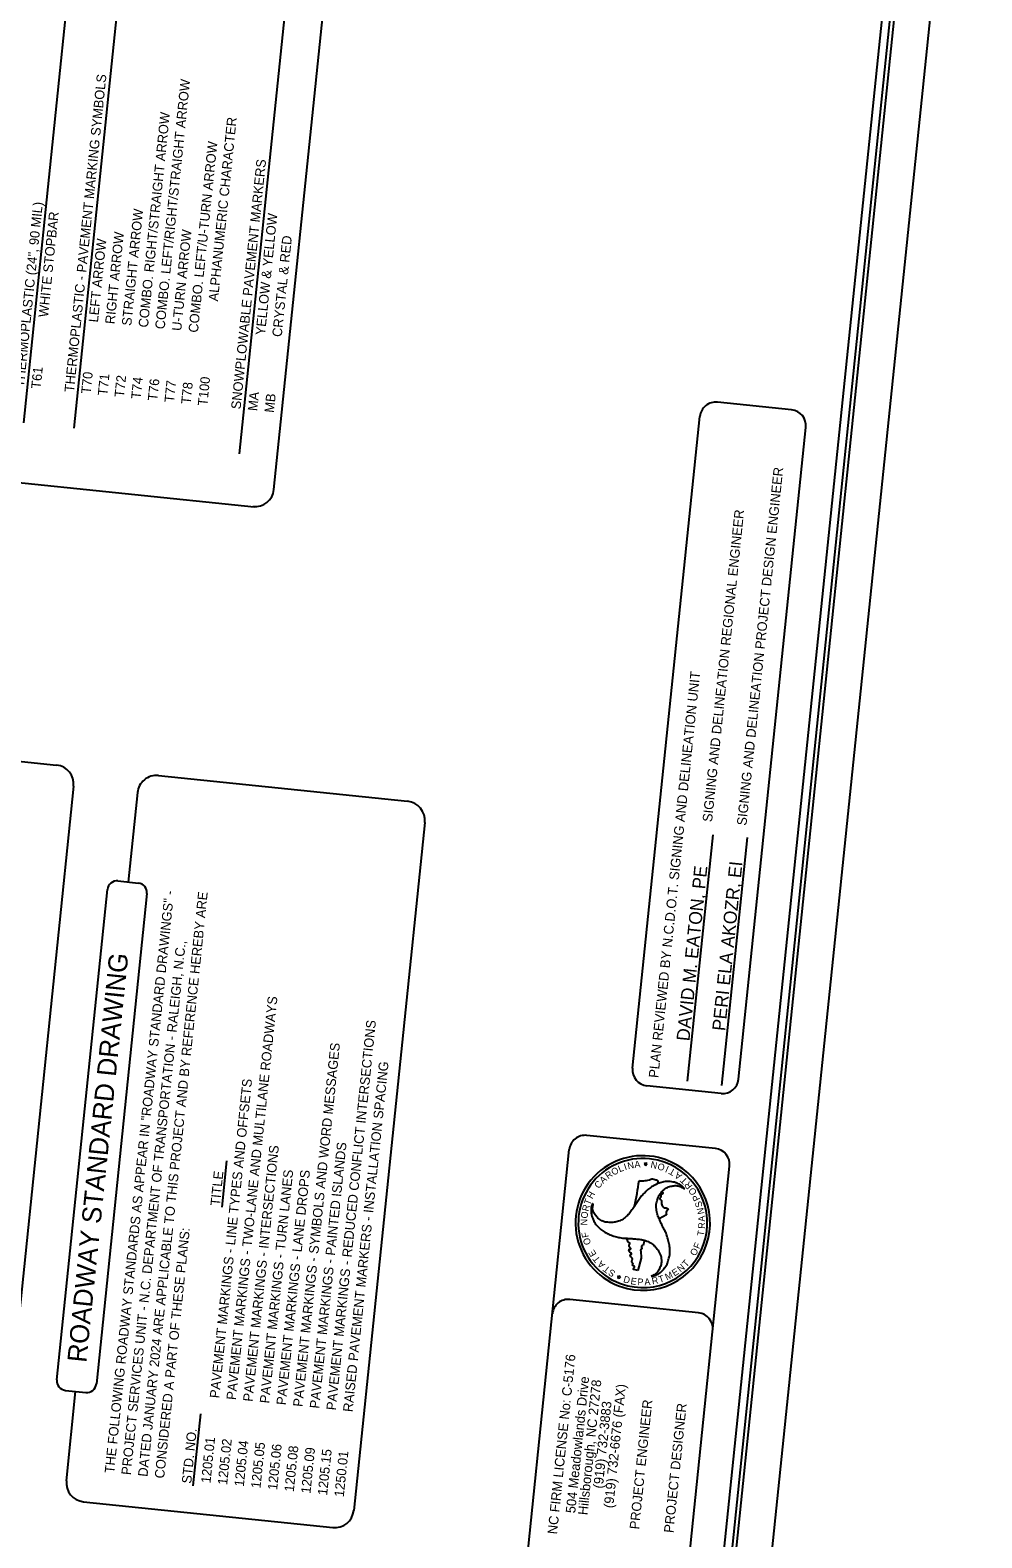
# Model space of a CAD drawing. Extents: x 2077770 to 2079037, y 247476 to 249877.
# Drawn here: x 2078441 to 2079037, y 248438 to 249383 of the extents above; entities that cross this region are included whole.
import ezdxf

# ---------------------------------------------------------------- set-up
doc = ezdxf.new("R2010")
doc.units = 0
for name, color, linetype in [('Default', 7, 'Continuous'), ('Prop DSN Text', 7, 'Continuous'), ('Sheet Data Field CELL', 7, 'Continuous'), ('Sheet Plot Border Inside CELL', 7, 'Continuous'), ('Sheet Plot Border Outside CELL', 7, 'Continuous'), ('Sheet Title CELL', 7, 'Continuous')]:
    doc.layers.add(name, color=color, linetype=linetype)

msp = doc.modelspace()

# ---------------------------------------------------------------- linework, layer by layer
at = {"layer": 'Default'}
for p, q in [((2078437.01, 249136.79), (2078468.87, 249445.46)), ((2078468.6, 249133.53), (2078500.46, 249442.19)), ((2078572.22, 249117.41), (2078604.08, 249426.08))]:
    msp.add_line(p, q, dxfattribs=at)
at = {"layer": 'Prop DSN Text'}
for p, q in [((2078561.18, 248645.5), (2078564.18, 248674.51)), ((2078543.17, 248470.98), (2078547.83, 248516.12))]:
    msp.add_line(p, q, dxfattribs=at)
at = {"layer": 'Sheet Plot Border Inside CELL'}
msp.add_lwpolyline([(2078843.53, 248043.45), (2079014.62, 249701.14), (2077965.1, 249809.47), (2077794, 248151.77)], close=True, dxfattribs=at)
at = {"layer": 'Sheet Plot Border Outside CELL'}
msp.add_lwpolyline([(2077943.23, 249816.25), (2077770.34, 248141.15), (2078864.51, 248028.21), (2079037.4, 249703.31)], close=True, dxfattribs=at)
at = {"layer": 'Sheet Title CELL'}
for p, q in [((2078858.5, 248262.08), (2079004.29, 249674.56)), ((2078593.75, 249095.03), (2078631.89, 249464.62)), ((2078918.18, 249144.97), (2078871.67, 249149.77)), ((2078818.55, 248732.54), (2078860.7, 249140.85)), ((2078884.96, 248725.69), (2078927.1, 249133.99)), ((2078214.68, 249121.93), (2078581.25, 249084.28)), ((2078190.95, 248949.99), (2078457.5, 248922.48)), ((2078468.2, 248909.31), (2078423.72, 248478.31)), ((2078521.32, 248915.9), (2078677.53, 248899.76)), ((2078508.16, 248905.2), (2078502.38, 248849.22)), ((2078688.23, 248886.59), (2078643.75, 248455.6)), ((2078852.97, 248724.49), (2078868.92, 248878.82)), ((2078874.45, 248721.72), (2078890.49, 248877.14)), ((2078457.7, 248537.42), (2078489.4, 248844.53)), ((2078514.12, 248841.98), (2078482.43, 248534.86)), ((2078495.98, 248849.88), (2078508.77, 248848.56)), ((2078873.99, 248716.77), (2078827.47, 248721.57)), ((2078870.42, 248682.21), (2078789.83, 248690.53)), ((2078738.74, 248293), (2078778.85, 248681.61)), ((2078826.46, 248672.82), (2078825.74, 248672.73)), ((2078825.74, 248672.73), (2078826.35, 248672.36)), ((2078826.35, 248672.36), (2078826.18, 248671.65)), ((2078826.18, 248671.65), (2078826.73, 248672.14)), ((2078826.6, 248673.52), (2078826.46, 248672.82)), ((2078826.9, 248672.84), (2078826.6, 248673.52)), ((2078826.73, 248672.14), (2078827.36, 248671.77)), ((2078827.63, 248672.89), (2078826.9, 248672.84)), ((2078827.08, 248672.41), (2078827.63, 248672.89)), ((2078827.36, 248671.77), (2078827.08, 248672.41)), ((2078834.7, 248676.65), (2078834.7, 248676.65)), ((2078839.23, 248282.62), (2078879.34, 248671.23)), ((2078793.44, 248647.77), (2078793.51, 248647.68)), ((2078793.44, 248647.77), (2078793.51, 248647.68)), ((2078819.68, 248646.13), (2078819.68, 248646.13)), ((2078839.74, 248640.7), (2078835.19, 248638.16)), ((2078835.19, 248638.16), (2078835.19, 248638.16)), ((2078825.88, 248624.85), (2078825.07, 248621.61)), ((2078823.73, 248618.3), (2078823.98, 248613.53)), ((2078821.82, 248605.82), (2078819.38, 248606.49)), ((2078823.98, 248613.53), (2078821.82, 248605.82)), ((2078809.04, 248602), (2078809.76, 248602.09)), ((2078809.65, 248601.65), (2078809.04, 248602)), ((2078809.48, 248600.93), (2078809.65, 248601.65)), ((2078810.04, 248601.4), (2078809.48, 248600.93)), ((2078809.76, 248602.09), (2078809.93, 248602.79)), ((2078809.93, 248602.79), (2078810.21, 248602.11)), ((2078810.68, 248601.03), (2078810.04, 248601.4)), ((2078810.21, 248602.11), (2078810.95, 248602.16)), ((2078810.95, 248602.16), (2078810.38, 248601.68)), ((2078810.38, 248601.68), (2078810.68, 248601.03)), ((2078859.82, 248579.45), (2078779.22, 248587.77)), ((2078463.05, 248530.83), (2078475.84, 248529.51)), ((2078463.67, 248474.2), (2078469.45, 248530.17)), ((2078474.38, 248461.03), (2078630.58, 248444.89))]:
    msp.add_line(p, q, dxfattribs=at)
msp.add_lwpolyline([(2078858.34, 248211.82), (2079009.26, 249674.05)], dxfattribs=at)
for centre, radius, start, end in [((2078870.64, 249139.82), 10, 84.10721, 174.10721), ((2078917.16, 249135.02), 10, 354.10721, 84.10721), ((2078581.81, 249096.27), 12, 264.10721, 354.10721), ((2078456.27, 248910.54), 12, 354.10721, 84.10721), ((2078520.09, 248903.96), 12, 84.10721, 174.10721), ((2078676.3, 248887.83), 12, 354.10721, 84.10721), ((2078495.37, 248843.91), 6, 84.10721, 174.10721), ((2078508.16, 248842.59), 6, 354.10721, 84.10721), ((2078828.5, 248731.51), 10, 174.10721, 264.10721), ((2078875.01, 248726.71), 10, 264.10721, 354.10721), ((2078788.8, 248680.58), 10, 84.10721, 174.10721), ((2078869.39, 248672.26), 10, 354.10721, 84.10721), ((2078824.89, 248635.64), 42.17, 76.52834, 256.52834), ((2078824.89, 248635.64), 40.42, 76.52834, 256.52834), ((2078824.89, 248635.64), 42.17, 256.52834, 76.52834), ((2078824.89, 248635.64), 40.42, 256.52834, 76.52834), ((2078602.47, 248693.7), 222.36, 347.64589, 351.8519), ((2078602.47, 248693.7), 222.36, 342.20683, 342.30643), ((2078778.2, 248577.82), 10, 84.10721, 174.10721), ((2078858.79, 248569.51), 10, 354.10721, 84.10721), ((2078463.67, 248536.8), 6, 174.10721, 264.10721), ((2078476.46, 248535.48), 6, 264.10721, 354.10721), ((2078475.61, 248472.97), 12, 174.10721, 264.10721), ((2078631.81, 248456.83), 12, 264.10721, 354.10721)]:
    msp.add_arc(centre, radius, start, end, dxfattribs=at)
for points in [[(2078851.09, 248656.84), (2078850.58, 248657.63), (2078848.47, 248659.5), (2078845.78, 248660.8), (2078845.51, 248660.9), (2078843.94, 248661.3), (2078842.06, 248661.54), (2078838.92, 248661.57), (2078835.83, 248660.81), (2078834.53, 248660.49), (2078833.18, 248659.81), (2078830.46, 248658.3), (2078828.13, 248656.56), (2078825.7, 248654.24), (2078823.72, 248652.05), (2078821.96, 248649.53), (2078820.27, 248646.98), (2078818.57, 248644.55), (2078816.75, 248642.02), (2078814.7, 248639.85), (2078814.5, 248639.68), (2078811.89, 248637.68), (2078809, 248636.55), (2078806.18, 248635.97), (2078804.74, 248635.9), (2078802.94, 248636.07), (2078801.9, 248636.13), (2078799.87, 248636.77), (2078797.28, 248638.27), (2078795.37, 248640.31), (2078794, 248642.5), (2078793.38, 248645.05), (2078793.51, 248647.68), (2078793.44, 248647.77)], [(2078822.59, 248662.18), (2078825.46, 248662.11), (2078829.03, 248662.77), (2078831.01, 248663.27), (2078832.52, 248662.88), (2078834.25, 248662.1), (2078834.01, 248660.3)], [(2078834.02, 248660.29), (2078833.18, 248659.81), (2078830.46, 248658.3), (2078828.13, 248656.56), (2078825.7, 248654.24), (2078823.72, 248652.05), (2078821.96, 248649.53), (2078820.27, 248646.98), (2078819.68, 248646.13)], [(2078830.21, 248602.37), (2078831.21, 248602.44), (2078833.86, 248603.33), (2078836.34, 248605), (2078836.52, 248605.2), (2078837.71, 248606.34), (2078838.81, 248607.85), (2078840.42, 248610.58), (2078841.3, 248613.61), (2078841.67, 248614.89), (2078841.76, 248616.45), (2078841.8, 248619.5), (2078841.47, 248622.38), (2078840.68, 248625.68), (2078839.79, 248628.47), (2078838.47, 248631.25), (2078837.08, 248634), (2078835.84, 248636.71), (2078834.6, 248639.52), (2078833.71, 248642.39), (2078833.67, 248642.7), (2078833.26, 248645.93), (2078833.7, 248648.96), (2078834.61, 248651.68), (2078835.26, 248653.05), (2078836.33, 248654.45), (2078836.89, 248655.36), (2078838.46, 248656.8), (2078841.03, 248658.25), (2078843.76, 248658.91), (2078846.36, 248659), (2078848.87, 248658.27), (2078851.09, 248656.84)], [(2078835.19, 248638.16), (2078834.6, 248639.52), (2078833.71, 248642.39), (2078833.67, 248642.7), (2078833.26, 248645.93), (2078833.7, 248648.96), (2078834.61, 248651.68), (2078835.26, 248653.05), (2078836.33, 248654.45), (2078836.86, 248655.29)], [(2078836.87, 248655.27), (2078837.5, 248654.72), (2078837.4, 248654.09), (2078836.28, 248653.22), (2078836.23, 248651.83), (2078835.73, 248651.31), (2078835.62, 248650.91), (2078836.59, 248649.66), (2078836.57, 248648.28), (2078837.63, 248645.77), (2078838.43, 248645.12), (2078840.44, 248644.8), (2078840.71, 248644.19), (2078840.46, 248643.58), (2078839.63, 248642.39), (2078839.74, 248640.7)], [(2078793.51, 248647.68), (2078793.04, 248646.81), (2078792.5, 248644.06), (2078792.72, 248641.08), (2078792.8, 248640.8), (2078793.2, 248639.24), (2078793.94, 248637.51), (2078795.51, 248634.78), (2078797.69, 248632.46), (2078798.63, 248631.51), (2078799.88, 248630.69), (2078802.55, 248629.09), (2078805.23, 248627.94), (2078808.46, 248626.98), (2078811.34, 248626.34), (2078814.38, 248626.11), (2078817.46, 248625.91), (2078820.43, 248625.65), (2078823.48, 248625.34), (2078826.41, 248624.65), (2078826.66, 248624.58), (2078829.66, 248623.31), (2078832.1, 248621.39), (2078834, 248619.21), (2078834.83, 248618), (2078835.57, 248616.37), (2078836, 248615.44), (2078836.51, 248613.35), (2078836.49, 248610.39), (2078835.67, 248607.68), (2078834.47, 248605.4), (2078832.59, 248603.59), (2078830.21, 248602.37)], [(2078819.38, 248606.49), (2078819.12, 248606.46), (2078818.96, 248606.94), (2078819.71, 248607.98), (2078819.35, 248608.69), (2078818.84, 248608.78), (2078818.46, 248609.36), (2078818.8, 248610.11), (2078818.06, 248611.05), (2078818.06, 248611.74), (2078818.39, 248613.13), (2078817.13, 248615.17), (2078817.2, 248615.88), (2078817.68, 248615.95), (2078817.87, 248616.35), (2078816.68, 248617.39), (2078816.52, 248617.61), (2078816.32, 248619.03), (2078816.65, 248619.31), (2078817.28, 248619.26), (2078817.44, 248619.41), (2078817.24, 248619.91), (2078816.65, 248620.66), (2078816.36, 248621.85), (2078816.79, 248623.01), (2078815.85, 248623.46), (2078815.24, 248625.09), (2078814.74, 248625.52), (2078814.18, 248625.73)], [(2078814.31, 248626.12), (2078814.38, 248626.11), (2078817.46, 248625.91), (2078820.43, 248625.65), (2078823.48, 248625.34), (2078825.88, 248624.83)], [(2078825.07, 248621.61), (2078824.39, 248621.44), (2078824.06, 248620.85), (2078824.31, 248619.89), (2078824.12, 248619.25), (2078823.44, 248618.67), (2078823.73, 248618.3)]]:
    msp.add_spline(points, degree=3, dxfattribs=at)

# ---------------------------------------------------------------- texts
at = {"layer": 'Prop DSN Text'}
for s, height, rotation, p in [('THERMOPLASTIC - PAVEMENT MARKING SYMBOLS', 6, 84.14501, (2078468.38, 249155.79)), ('T76              COMBO. LEFT/RIGHT/STRAIGHT ARROW', 6, 84.14501, (2078520.59, 249150.43)), ('T74              COMBO. RIGHT/STRAIGHT ARROW', 6, 84.14501, (2078510.15, 249151.5)), ('        ALPHANUMERIC CHARACTER ', 6, 84.14501, (2078556.81, 249194.97)), ('T78              COMBO. LEFT/U-TURN ARROW', 6, 84.14501, (2078541.48, 249148.29)), ('SNOWPLOWABLE PAVEMENT MARKERS', 6, 84.14501, (2078572.8, 249145.08)), ('THERMOPLASTIC (24", 90 MIL)', 6, 84.14501, (2078437.05, 249159)), ('T61              WHITE STOPBAR', 6, 84.14501, (2078447.5, 249157.93)), ('T72              STRAIGHT ARROW', 6, 84.14501, (2078499.71, 249152.58)), ('MA                YELLOW & YELLOW', 6, 84.14501, (2078583.24, 249144.01)), ('T71              RIGHT ARROW', 6, 84.14501, (2078489.26, 249153.65)), ('T77              U-TURN ARROW', 6, 84.14501, (2078531.03, 249149.36)), ('T70              LEFT ARROW', 6, 84.14501, (2078478.82, 249154.72)), ('MB                CRYSTAL & RED', 6, 84.14501, (2078593.69, 249142.94)), ('T100', 6, 84.14501, (2078551.92, 249147.22)), ('PLAN REVIEWED BY N.C.D.O.T. SIGNING AND DELINEATION UNIT', 6.075, 84.10721, (2078834.62, 248726.29)), ('THE FOLLOWING ROADWAY STANDARDS AS APPEAR IN "ROADWAY STANDARD DRAWINGS" - ', 6, 84.10721, (2078493.57, 248478.67)), ('DATED JANUARY 2024 ARE APPLICABLE TO THIS PROJECT AND BY REFERENCE HEREBY ARE', 6, 84.10721, (2078514.45, 248476.51)), ('ROADWAY STANDARD DRAWING', 12, 84.10721, (2078476.12, 248547.89)), ('PROJECT SERVICES UNIT - N.C. DEPARTMENT OF TRANSPORTATION - RALEIGH, N.C.,', 6, 84.10721, (2078504.01, 248477.59)), ('1205.02           PAVEMENT MARKINGS - TWO-LANE AND MULTILANE ROADWAYS', 6, 84.10721, (2078564.38, 248471.36)), ('1205.15           PAVEMENT MARKINGS - REDUCED CONFLICT INTERSECTIONS', 6, 84.10721, (2078627.02, 248464.89)), ('1205.08           PAVEMENT MARKINGS - SYMBOLS AND WORD MESSAGES', 6, 84.10721, (2078606.14, 248467.05)), ('1250.01           RAISED PAVEMENT MARKERS - INSTALLATION SPACING', 6, 84.10721, (2078637.47, 248463.81)), ('1205.01           PAVEMENT MARKINGS - LINE TYPES AND OFFSETS', 6, 84.10721, (2078553.93, 248472.44)), ('1205.04           PAVEMENT MARKINGS - INTERSECTIONS', 6, 84.10721, (2078574.82, 248470.28)), ('1205.09           PAVEMENT MARKINGS - PAINTED ISLANDS', 6, 84.10721, (2078616.58, 248465.97)), ('TITLE', 6, 84.10721, (2078559.86, 248646.21)), ('1205.05           PAVEMENT MARKINGS - TURN LANES', 6, 84.10721, (2078585.26, 248469.2)), ('1205.06           PAVEMENT MARKINGS - LANE DROPS', 6, 84.10721, (2078595.7, 248468.12)), ('CONSIDERED A PART OF THESE PLANS:', 6, 84.10721, (2078524.9, 248475.43)), ('NC FIRM LICENSE No: C-5176', 6, 84.10721, (2078771.13, 248440.48)), ('504 Meadowlands Drive', 6, 84.10721, (2078782.51, 248453.66)), ('Hillsborough, NC 27278', 6, 84.10721, (2078790.23, 248452.47)), ('(919) 732-6676 (FAX)', 6, 84.10721, (2078806.35, 248456.85)), ('(919) 732-3883', 6, 84.10721, (2078799.78, 248469.13)), ('STD. NO.', 6, 84.10721, (2078541.89, 248472.17))]:
    msp.add_text(s, height=height, rotation=rotation, dxfattribs=at).set_placement(p)
at = {"layer": 'Sheet Data Field CELL'}
for s, p in [('PERI ELA AKOZR, EI', (2078876.52, 248755.67)), ('DAVID M. EATON, PE', (2078854.11, 248749.3))]:
    msp.add_text(s, height=8.2032, rotation=84.10721, dxfattribs=at).set_placement(p)
at = {"layer": 'Sheet Title CELL'}
for s, height, rotation, p in [('SIGNING AND DELINEATION PROJECT DESIGN ENGINEER', 6, 84.10721, (2078889.81, 248884.38)), ('SIGNING AND DELINEATION REGIONAL ENGINEER', 6, 84.10721, (2078868.28, 248886.61)), ('L', 4.19, 22.11312, (2078810.43, 248667.38)), ('I', 4.21, 18.12378, (2078813.82, 248668.67)), ('N', 4.2, 12.42367, (2078815.78, 248669.28)), ('A', 4.21, 4.9917, (2078819.82, 248670.14)), ('N', 4.21, 168.73647, (2078834.33, 248673.59)), ('O', 4.19, 161.48845, (2078839.16, 248672.03)), ('I', 4.22, 156.35283, (2078841.65, 248670.97)), ('C', 4.19, 49.32738, (2078797.24, 248656.87)), ('A', 4.2, 41.83035, (2078799.99, 248660.05)), ('R', 4.2, 35.4664, (2078803.2, 248662.93)), ('O', 4.21, 28.3468, (2078806.48, 248665.25)), ('T', 4.2, 150.70292, (2078845.8, 248668.66)), ('A', 4.21, 143.6185, (2078849.84, 248665.75)), ('T', 4.19, 135.53145, (2078853.3, 248662.47)), ('R', 4.21, 129.43167, (2078856.3, 248658.91)), ('H', 4.2, 61.66973, (2078793.29, 248650.37)), ('O', 4.21, 122.24256, (2078859.04, 248654.63)), ('P', 4.2, 115.55057, (2078861.02, 248650.58)), ('O', 4.22, 82.01401, (2078790.14, 248638.24)), ('R', 4.21, 75.40408, (2078790.76, 248642.64)), ('T', 4.22, 68.75445, (2078791.77, 248646.54)), ('S', 4.19, 108.35872, (2078862.51, 248646.18)), ('N', 4.19, 101.14825, (2078863.51, 248641.53)), ('N', 4.21, 89.51212, (2078790.08, 248634.13)), ('A', 4.19, 94.11662, (2078863.95, 248636.58)), ('R', 4.21, 87.36349, (2078863.8, 248631.93)), ('F', 4.21, 101.59906, (2078791.16, 248626.89)), ('O', 4.21, 108.7459, (2078792.57, 248622.67)), ('F', 4.2, 67.49764, (2078860.28, 248619.09)), ('T', 4.19, 80.40687, (2078863.06, 248627.23)), ('E', 4.19, 120.68528, (2078796.05, 248616.08)), ('T', 4.2, 127.8009, (2078798.56, 248612.82)), ('O', 4.2, 60.33241, (2078857.83, 248614.63)), ('A', 4.22, 134.85612, (2078801.63, 248609.73)), ('T', 4.21, 141.90844, (2078804.83, 248607.15)), ('S', 4.2, 148.28459, (2078808.23, 248605.04)), ('M', 4.19, 25.7484, (2078840.02, 248599.65)), ('E', 4.19, 33.21518, (2078844.8, 248602.05)), ('N', 4.21, 40.18672, (2078848.57, 248604.58)), ('T', 4.2, 47.02872, (2078852.17, 248607.68)), ('D', 4.21, 344.38134, (2078812.35, 248598.65)), ('E', 4.19, 350.66923, (2078817.02, 248597.39)), ('P', 4.21, 358.20162, (2078821.54, 248596.73)), ('A', 4.2, 4.79419, (2078826.03, 248596.6)), ('R', 4.2, 11.86283, (2078830.99, 248597.07)), ('T', 4.2, 18.51336, (2078835.52, 248598.06)), ('PROJECT ENGINEER', 6, 84.10721, (2078822.55, 248443.54)), ('PROJECT DESIGNER', 6, 84.10721, (2078844.08, 248441.32))]:
    msp.add_text(s, height=height, rotation=rotation, dxfattribs=at).set_placement(p)

doc.saveas('drawing.dxf')
